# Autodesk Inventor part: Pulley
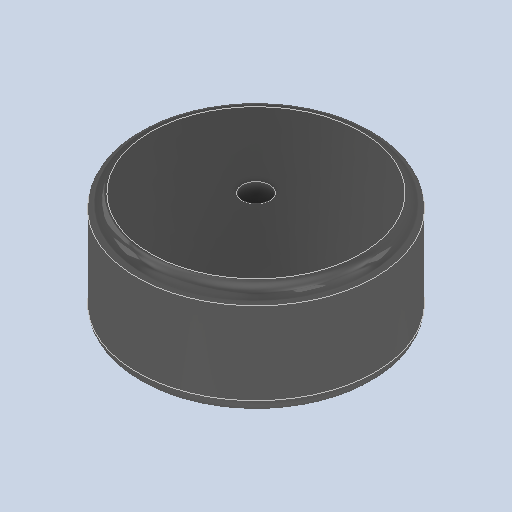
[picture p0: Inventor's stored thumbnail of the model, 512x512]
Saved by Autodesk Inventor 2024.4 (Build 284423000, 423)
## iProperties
Created: 2025-07
Part Number: Pulley
Material: Generic
Document SubType Name: Modeling
Designer: AdminForWorker
Density: 1 g/cm^3
Appearance: Default
Title: Pulley v1
Author: AdminForWorker
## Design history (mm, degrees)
feature "Body1"
body "Solid1"
